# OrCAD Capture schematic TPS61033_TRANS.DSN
size C
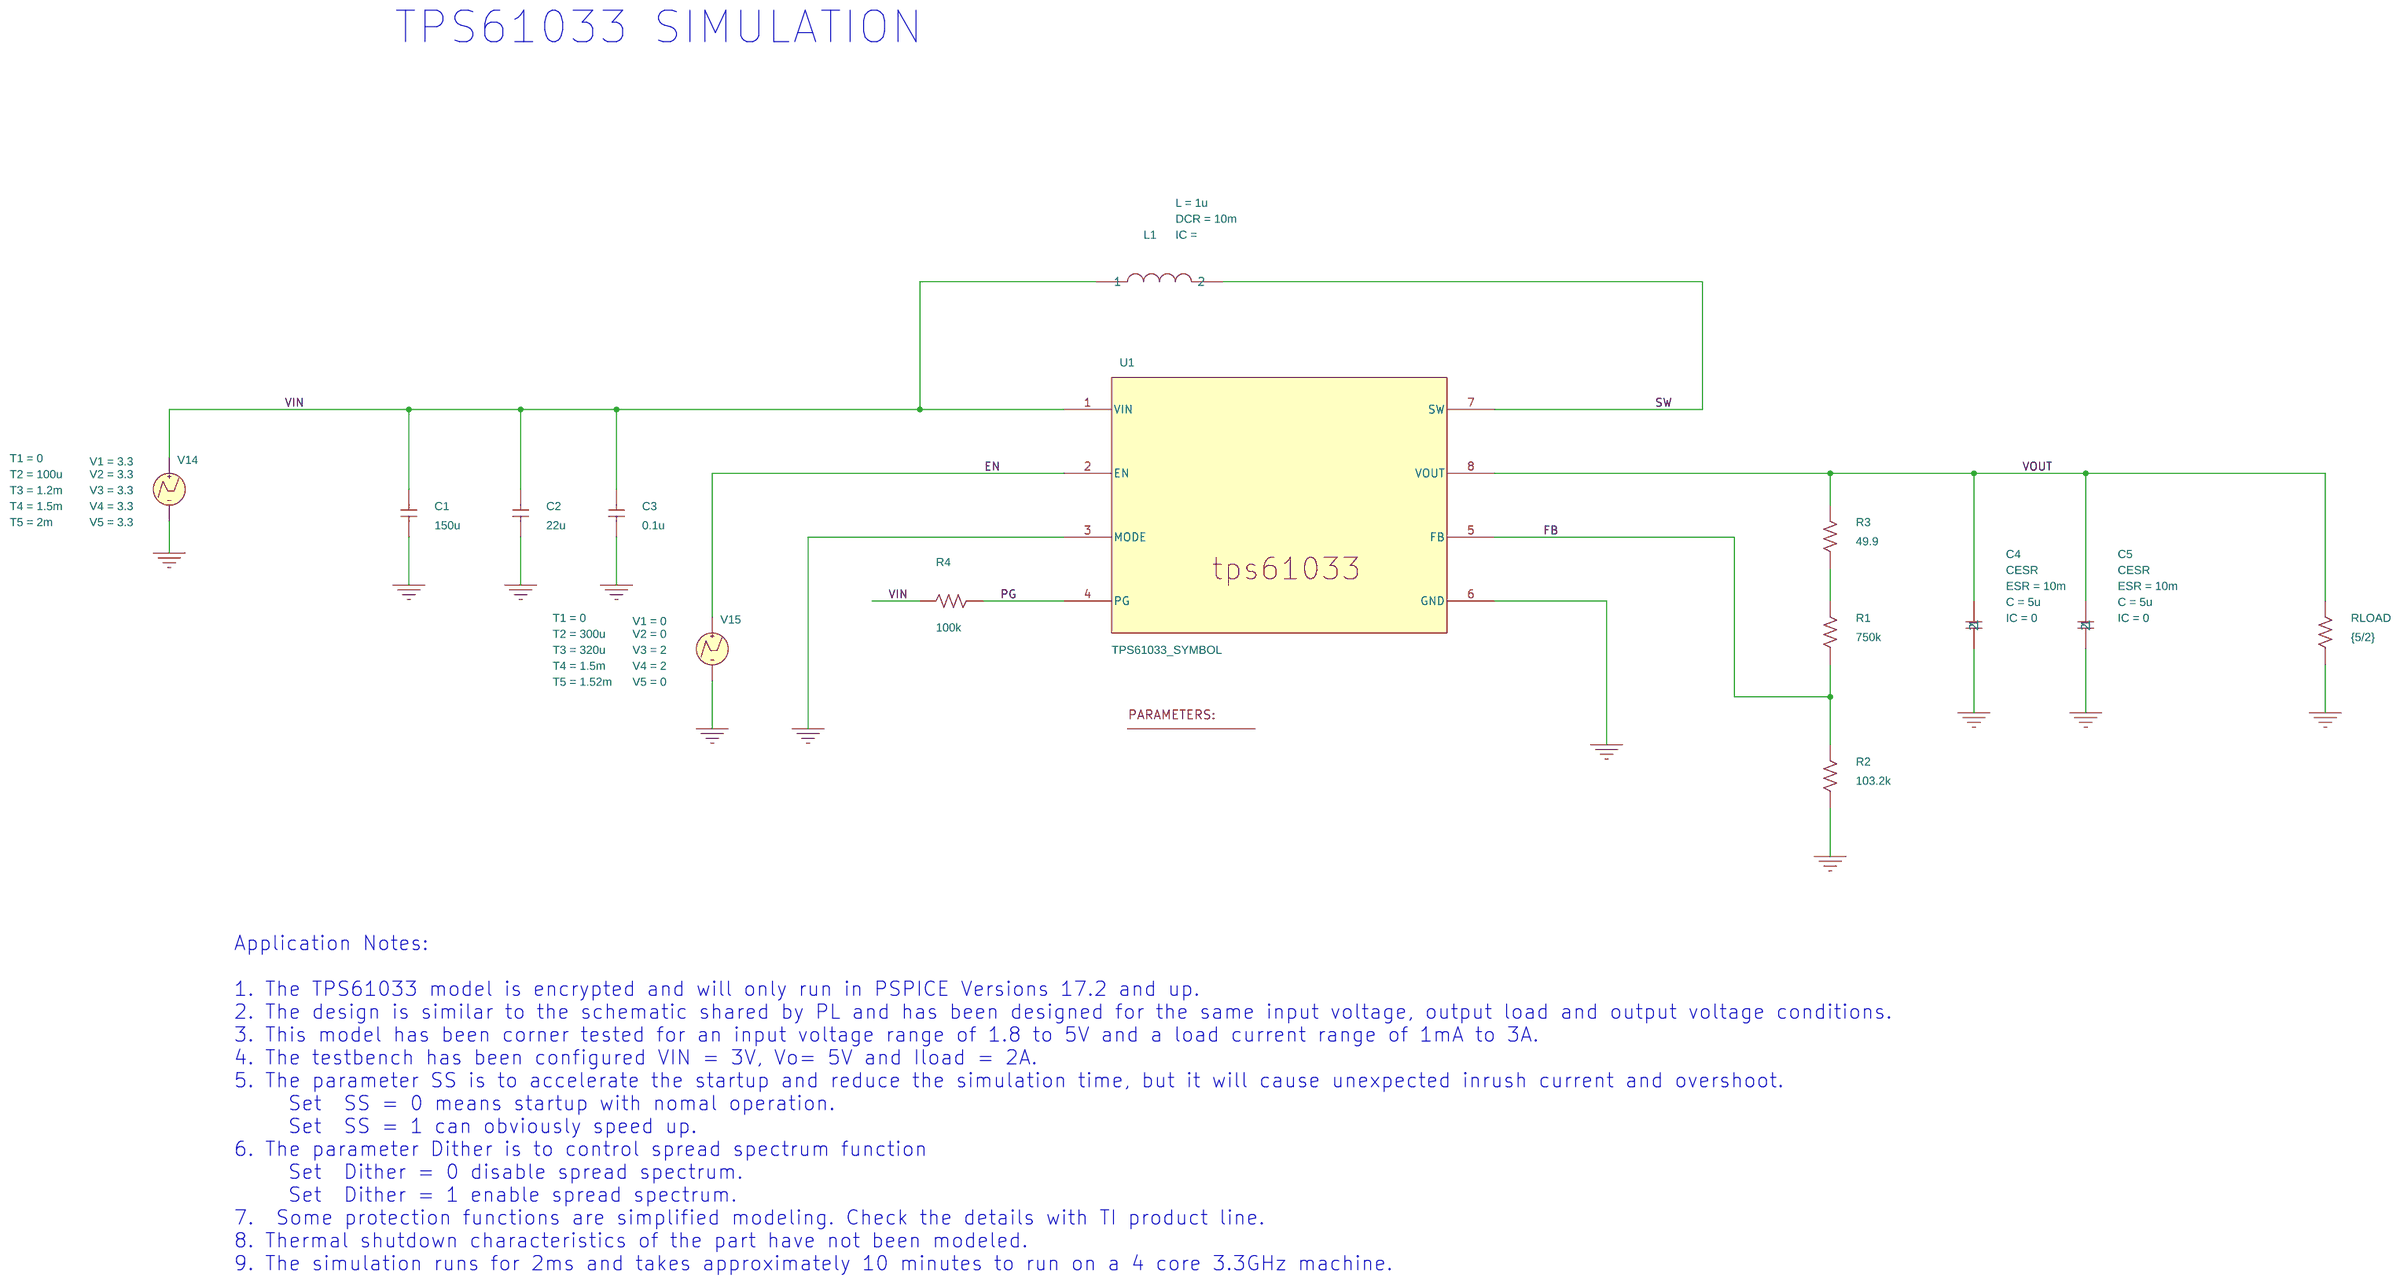
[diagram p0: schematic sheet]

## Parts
1  PARAM
C1  150u  [RAD/CK05]
C2  22u  [RAD/CK05]
C3  0.1u  [RAD/CK05]
C4  CESR
C5  CESR
L1  LDCR
R1  750k  [AX/RC05]
R2  103.2k  [AX/RC05]
R3  49.9  [AX/RC05]
R4  100k  [AX/RC05]
RLOAD  {5/2}  [AX/RC05]
U1  TPS61033_SYMBOL
V14  VPWL
V15  VPWL

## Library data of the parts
1 = PARAM: Dither: 0; SS: 0
C1-C3 = C
C4 = CESR_1: C: 5u; ESR: 10m; IC: 0; PSpiceTemplate: X^@REFDES %1 %2 @MODEL PARAMS: ?C|C=@C||C=10U| ?ESR|ESR=@ESR||ESR=2M| ?IC|IC=@IC||IC=1N| ?X|X=@X||X=1|; X: 1
C5 = CESR: C: 5u; ESR: 10m; IC: 0; PSpiceTemplate: X^@REFDES %1 %2 @MODEL PARAMS: ?C|C=@C||C=10U| ?ESR|ESR=@ESR||ESR=2M| ?IC|IC=@IC||IC=1N| ?X|X=@X||X=1|; X: 1
L1 = LDCR: DCR: 10m; L: 1u
R1-R4 RLOAD = R
U1 = TPS61033_SYMBOL_2
V14 = VPWL: PSpiceTemplate: V^@REFDES %+ %- ?DC|DC @DC| ?AC|AC @AC|\n+PWL @T1 @V1 @T2 @V2 #T3/@T3 @V3/ #T4/@T4 @V4/ #T5/@T5 @V5/ #T6/@T6 @V6/ #T7/@T7 @V7/ #T8/@T8 @V8/ #T9/@T9 @V9/ #T10/@T10 @V10/; T1: 0; T2: 100u; T3: 1.2m; T4: 1.5m; T5: 2m; V1: 3.3; V2: 3.3; V3: 3.3; V4: 3.3; V5: 3.3
V15 = VPWL: PSpiceTemplate: V^@REFDES %+ %- ?DC|DC @DC| ?AC|AC @AC|\n+PWL @T1 @V1 @T2 @V2 #T3/@T3 @V3/ #T4/@T4 @V4/ #T5/@T5 @V5/ #T6/@T6 @V6/ #T7/@T7 @V7/ #T8/@T8 @V8/ #T9/@T9 @V9/ #T10/@T10 @V10/; T1: 0; T2: 300u; T3: 320u; T4: 1.5m; T5: 1.52m; V1: 0; V2: 0; V3: 2; V4: 2; V5: 0

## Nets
VIN: C1.2 C2.2 C3.2 L1.1 R4.2 U1.1(VIN) V14.1(+)
0: C1.1 C2.1 C3.1 C4.2 C5.2 R2.1 RLOAD.1 U1.3(MODE) U1.6(GND) V14.2(-) V15.2(-)
EN: U1.2(EN) V15.1(+)
FB: R1.1 R2.2 U1.5(FB)
PG: R4.1 U1.4(PG)
SW: L1.2 U1.7(SW)
VOUT: C4.1 C5.1 R3.2 RLOAD.2 U1.8(VOUT)
N393462: R1.2 R3.1

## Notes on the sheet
- TPS61033 SIMULATION
- Application Notes:
  1. The TPS61033 model is encrypted and will only run in PSPICE Versions 17.2 and up.
  2. The design is similar to the schematic shared by PL and has been designed for the same input voltage, output load and output voltage conditions.
  3. This model has been corner tested for an input voltage range of 1.8 to 5V and a load current range of 1mA to 3A.
  4. The testbench has been configured VIN = 3V, Vo= 5V and Iload = 2A.
  5. The parameter SS is to accelerate the startup and reduce the simulation time, but it will cause unexpected inrush current and overshoot.
       Set  SS = 0 means startup with nomal operation.
       Set  SS = 1 can obviously speed up.
  6. The parameter Dither is to control spread spectrum function
       Set  Dither = 0 disable spread spectrum.
       Set  Dither = 1 enable spread spectrum.
  7.  Some protection functions are simplified modeling. Check the details with TI product line.
  8. Thermal shutdown characteristics of the part have not been modeled.
  9. The simulation runs for 2ms and takes approximately 10 minutes to run on a 4 core 3.3GHz machine.
